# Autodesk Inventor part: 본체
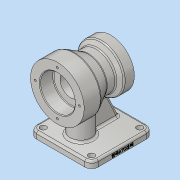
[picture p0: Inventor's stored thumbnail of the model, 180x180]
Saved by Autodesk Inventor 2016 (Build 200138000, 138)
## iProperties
Created: 2019-01
Part Number: 본체
Material: 알루미늄 6061
Document SubType Name: Modeling
Designer: Administrator
Density: 2.7 g/cm^3
Appearance: 알루미늄 - 평지
Mass: 898.816 g
Surface Area: 600.964 cm^2
Volume: 332.895 cm^3
Author: Administrator
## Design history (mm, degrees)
sketch "스케치1"
  geometry: L1 (-40, 0)-(40, 0); L2 (-40, 0)-(-40, 40); L3 (-40, 40)-(-15, 40); L4 (-15, 40)-(5.785, 28); L5 (5.785, 28)-(19.126, 28); L6 (19.126, 28)-(25, 35); L7 (25, 35)-(40, 35); L8 (40, 35)-(40, 0); 1 further point
  constraints: 16 end point, 2 midpoint, 2 parallel, 2 perpendicular, 1 horizontal, 1 vertical
  dimensions: "d0" = 80 distance of L1.start L1.end; "d1" = 80 diameter of L3 L1; "d2" = 56 diameter of L5 L1; "d3" = 70 diameter of L7 L1; "d4" = 25 distance of L2.end L3.end; "d5" = 15 distance of L6.end L7.end; "d6" = 30 deg angle of L5 L4; "d7" = 50 deg angle of L6 L5
revolve "회전1" sketch "스케치1" stored, may be unused: angle "d8" = 90 deg
node "작업 평면1"
sketch "스케치2"
  geometry: L1 (40, -40)-(-40, -40) reference; L2 (-46, -35)-(46, -35); L3 (46, -35)-(46, 57); L4 (46, 57)-(-46, 57); L5 (-46, 57)-(-46, -35); L6 (-46, -35)-(46, 57); L7 (46, -35)-(-46, 57); 3 further points
  constraints: 12 end point, 3 midpoint, 2 parallel, 1 horizontal, 1 perpendicular, 1 vertical alignment
  dimensions: "d10" = 92 distance of L4.end L3.end; "d11" = 92 distance of L3.end L2.end; "d12" = 5 distance between parallel lines of L1 L2
extrude "돌출1" join sketch "스케치2" distance "d13" = 10; taper "d14" = 0 deg
sketch "스케치3"
  geometry: L1 (-46, -35)-(46, -35) reference; L2 (-46, 57)-(-46, -35) reference; L3 (-5, 18.605)-(5, 18.605); L4 (5, 18.605)-(5, 10.199); L5 (-5, 10.199)-(-5, 18.605); A1 r 16 centre (0, -5) between (-5, 10.199) and (5, 10.199); 2 further points
  constraints: 6 end point, 2 point on circle, 1 centre point, 1 horizontal, 1 parallel, 1 perpendicular, 1 vertical alignment
  dimensions: "d15" = 30 distance from line of L1 A1.centre; "d16" = 46 distance from line of L2 A1.centre; "d17" = 16 radius of A1; "d18" = 10 distance of L3.start L3.end
extrude "돌출2" join sketch "스케치3" stored distance "d19" = 10; taper "d20" = 0 deg
sketch "스케치4"
  geometry: L1 (-35, -70)-(57, -70) reference; L2 (47, -70)-(37.491, -49.608); L3 (57, -80)-(57, -70) reference; 1 further point
  constraints: 2 end point, 1 point on line
  dimensions: "d21" = 10 distance from line of L3 L2.start; "d22" = 25 deg angle of L3 L2
feature "리브1" sketch "스케치4" dims "d23" = 1, "d24" = 10, "d25" = 0, "d26" = 0, "d27" = 1, "d28" = 1
sketch "스케치5"
  geometry: C1 r 26 at (0, 0); 1 further point
  constraints: 1 centre point, 1 coincident
  dimensions: "d29" = 52 diameter of C1
extrude "돌출3" cut sketch "스케치5" distance "d30" = 20; taper "d31" = 0 deg
sketch "스케치6"
  geometry: C1 r 20 at (0, 0); 1 further point
  constraints: 1 centre point, 1 coincident
  dimensions: "d32" = 40 diameter of C1
extrude "돌출4" cut sketch "스케치6" distance "d33" = 17; taper "d34" = 0 deg
sketch "스케치7"
  geometry: C1 r 16 at (0, 0); 1 further point
  constraints: 1 centre point, 1 coincident
  dimensions: "d35" = 32 diameter of C1
extrude "돌출5" cut sketch "스케치7" stored distance "d36" = 17; taper "d37" = 0 deg
sketch "스케치8"
  geometry: 2 further points
  constraints: 1 vertical alignment
  dimensions: "d38" = 33 distance of point (0, 0) point (0, 33)
hole "구멍1" sketch "스케치8" at (0, 33) diameter "d39" = 3.242; stored, may be unused: countersink angle "d43" = 90 deg, drill point angle "d45" = 118 deg; dims "d40" = 9, "d41" = 4, "d42" = 2, "d44" = 11
sketch "스케치9"
  geometry: 2 further points
  constraints: 1 vertical alignment
  dimensions: "d49" = 27.5 distance of point (0, 0) point (0, -27.5)
hole "구멍2" sketch "스케치9" at (0, -27.5) diameter "d50" = 3.242; stored, may be unused: countersink angle "d54" = 90 deg, drill point angle "d56" = 118 deg; dims "d51" = 9, "d52" = 4, "d53" = 2, "d55" = 11
chamfer "모따기1" distance "d60" = 1; stored, may be unused: second distance "d61" = 2, angle "d62" = 45 deg
fillet "모깎기1" dims "d63" = 1
fillet "모깎기2" dims "d64" = 0.6
fillet "모깎기3" dims "d65" = 10
hole "구멍3" diameter "d68" = 9; stored, may be unused: countersink angle "d72" = 90 deg, drill point angle "d74" = 118 deg; dims "d66" = 10, "d67" = 10, "d69" = 9, "d70" = 4, "d71" = 2, "d73" = 11
fillet "모깎기4" dims "d81" = 3
fillet "모깎기5" dims "d82" = 3
fillet "모깎기6" dims "d83" = 3
fillet "모깎기7" dims "d84" = 3
fillet "모깎기8" dims "d85" = 3
sketch "스케치10"
  geometry: L1 (0, 0)-(0, 72) reference; L2 (-7, -10)-(0, -10) reference; 2 further points
  constraints: 1 other
  dimensions: "d86" = 4 distance from line of L1 point (-4, 36); "d87" = 46 distance from line of L2 point (-4, 36)
feature "엠보싱1" sketch "스케치10" dims "d88" = 0.5, "d89" = 0
feature "분할1"
node "솔리드1"
pattern_circular "원형 패턴1" dims angle "d47" = 360 deg
pattern_circular "원형 패턴2" dims angle "d58" = 360 deg
pattern_linear "직사각형 패턴1" dims "d77" = 72, "d80" = 72
